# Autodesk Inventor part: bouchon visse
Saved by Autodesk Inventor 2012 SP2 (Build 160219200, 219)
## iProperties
Created: 2013-04
Part Number: bouchon visse
Material: Default
Document SubType Name: Modeling
Designer: papa
Density: 1 g/cm^3
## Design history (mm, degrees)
node "bouchon visse1"
node "bouchon visse"
node "Base1"
